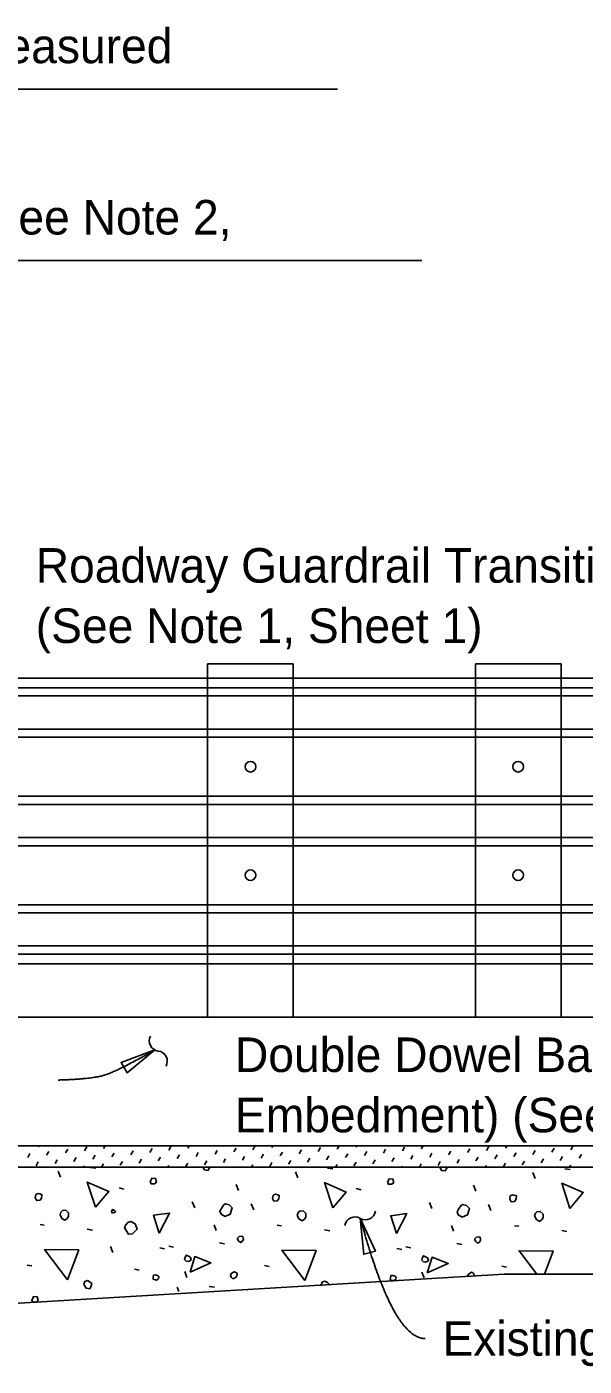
# Model space of a CAD drawing. Extents: x 0 to 41.1, y 0 to 25.9.
# Drawn here: x 30.12 to 33.37, y 5.83 to 13.65 of the extents above; entities that cross this region are included whole.
import ezdxf

# ---------------------------------------------------------------- set-up
doc = ezdxf.new("R2010")
doc.units = 0
for name, color, linetype in [('Dimension', 7, 'Continuous'), ('ExistSuperStruct', 7, 'Continuous'), ('Miscellaneous', 7, 'Continuous'), ('SteelMisc_h', 7, 'Continuous'), ('TextStructures', 7, 'Continuous')]:
    doc.layers.add(name, color=color, linetype=linetype)

msp = doc.modelspace()

# ---------------------------------------------------------------- linework, layer by layer
at = {"layer": 'Dimension'}
for p, q in [((31.9321, 13.2856), (20.3986, 13.2856)), ((32.4255, 12.2857), (27.1158, 12.2857))]:
    msp.add_line(p, q, dxfattribs=at)
for points in [[(30.8674, 7.6796), (30.7047, 7.5449), (30.6694, 7.606)], [(32.0659, 6.6961), (32.086, 6.4858), (32.1541, 6.5042)]]:
    msp.add_lwpolyline(points, close=True, dxfattribs=at)
for centre, start, end in [((30.894, 7.7311), 151.52667, 263.25389), ((30.88, 7.6127), 331.52667, 83.25389), ((32.096, 6.7468), 239.26505, 350.99227), ((32.0351, 6.6444), 59.26505, 170.99227)]:
    msp.add_arc(centre, 0.0596, start, end, dxfattribs=at)
for points in [[(30.3034, 7.5026), (30.4844, 7.5075), (30.6433, 7.5501), (30.8674, 7.6796)], [(32.0663, 6.6959), (32.2554, 5.9941), (32.4446, 5.9941)]]:
    msp.add_open_spline(points, degree=2, dxfattribs=at)
at = {"layer": 'ExistSuperStruct'}
for p, q in [((27.6853, 7.8689), (35.7954, 7.8689)), ((39.26, 7.1191), (27.6853, 7.1191)), ((27.6853, 6.994), (39.26, 6.994)), ((32.9053, 6.369), (28.6853, 6.119)), ((39.26, 6.369), (32.9053, 6.369))]:
    msp.add_line(p, q, dxfattribs=at)
at = {"layer": 'Miscellaneous'}
for p, q in [((31.1749, 9.9315), (31.1749, 7.869)), ((31.1749, 9.9315), (31.6749, 9.9315)), ((31.6749, 9.9315), (31.6749, 7.869)), ((32.7374, 9.9315), (32.7374, 7.869)), ((32.7374, 9.9315), (33.2374, 9.9315)), ((33.2374, 9.9315), (33.2374, 7.869)), ((26.2319, 9.7925), (37.5468, 9.7925)), ((26.2319, 9.7443), (37.5468, 9.7443)), ((26.2319, 9.5515), (37.5468, 9.5515)), ((26.2319, 9.5032), (37.5468, 9.5032)), ((26.2319, 9.1593), (37.5468, 9.1593)), ((26.2319, 9.1111), (37.5468, 9.1111)), ((26.2319, 8.9182), (37.5468, 8.9182)), ((26.2319, 8.8701), (37.5468, 8.8701)), ((26.2319, 8.5262), (37.5468, 8.5262)), ((26.2319, 8.4779), (37.5468, 8.4779)), ((26.2319, 8.2851), (37.5468, 8.2851)), ((26.2319, 8.2369), (37.5468, 8.2369)), ((30.1865, 7.1128), (30.1901, 7.1191)), ((30.5673, 7.1029), (30.5766, 7.1191)), ((30.6779, 7.1158), (30.6798, 7.1191)), ((30.948, 7.0929), (30.961, 7.1153)), ((31.0586, 7.1059), (31.0663, 7.1191)), ((31.1693, 7.1189), (31.1694, 7.1191)), ((31.4394, 7.096), (31.4523, 7.1183)), ((31.55, 7.1089), (31.5559, 7.1191)), ((31.9307, 7.099), (31.9424, 7.1191)), ((32.0414, 7.1119), (32.0455, 7.1191)), ((32.4221, 7.102), (32.432, 7.1191)), ((32.5327, 7.115), (32.5351, 7.1191)), ((32.8028, 7.0921), (32.8158, 7.1144)), ((32.9135, 7.105), (32.9216, 7.1191)), ((33.0241, 7.118), (33.0247, 7.1191)), ((33.2942, 7.0951), (33.3072, 7.1175)), ((30.1247, 7.051), (30.1377, 7.0734)), ((30.2354, 7.064), (30.2483, 7.0864)), ((30.2842, 7.0152), (30.2972, 7.0375)), ((30.346, 7.077), (30.359, 7.0993)), ((30.3948, 7.0281), (30.4078, 7.0505)), ((30.4566, 7.0899), (30.4696, 7.1123)), ((30.5055, 7.0411), (30.5184, 7.0635)), ((30.6161, 7.054), (30.6291, 7.0764)), ((30.7267, 7.067), (30.7397, 7.0894)), ((30.7756, 7.0182), (30.7885, 7.0406)), ((30.8374, 7.08), (30.8503, 7.1024)), ((30.8862, 7.0311), (30.8992, 7.0535)), ((30.9968, 7.0441), (31.0098, 7.0665)), ((31.1075, 7.0571), (31.1204, 7.0795)), ((31.2181, 7.07), (31.2311, 7.0924)), ((31.2669, 7.0212), (31.2799, 7.0436)), ((31.3287, 7.083), (31.3417, 7.1054)), ((31.3776, 7.0342), (31.3905, 7.0566)), ((31.4882, 7.0471), (31.5012, 7.0695)), ((31.5988, 7.0601), (31.6118, 7.0825)), ((31.7095, 7.073), (31.7224, 7.0954)), ((31.7583, 7.0242), (31.7713, 7.0466)), ((31.8201, 7.086), (31.8331, 7.1084)), ((31.8689, 7.0372), (31.8819, 7.0596)), ((31.9796, 7.0501), (31.9925, 7.0725)), ((32.0902, 7.0631), (32.1032, 7.0855)), ((32.139, 7.0143), (32.152, 7.0367)), ((32.2008, 7.0761), (32.2138, 7.0985)), ((32.2497, 7.0272), (32.2626, 7.0496)), ((32.3115, 7.089), (32.3244, 7.1114)), ((32.3603, 7.0402), (32.3733, 7.0626)), ((32.4709, 7.0532), (32.4839, 7.0756)), ((32.5816, 7.0661), (32.5945, 7.0885)), ((32.6304, 7.0173), (32.6434, 7.0397)), ((32.6922, 7.0791), (32.7052, 7.1015)), ((32.741, 7.0303), (32.754, 7.0526)), ((32.8517, 7.0432), (32.8646, 7.0656)), ((32.9623, 7.0562), (32.9753, 7.0786)), ((33.0729, 7.0691), (33.0859, 7.0915)), ((33.1218, 7.0203), (33.1347, 7.0427)), ((33.1836, 7.0821), (33.1965, 7.1045)), ((33.2324, 7.0333), (33.2454, 7.0557)), ((33.343, 7.0462), (33.356, 7.0686)), ((30.1736, 7.0022), (30.1865, 7.0246)), ((30.317, 6.9356), (30.3029, 6.971)), ((30.4522, 6.994), (30.4566, 7.0017)), ((30.4896, 6.9916), (30.5214, 6.988)), ((30.5553, 6.994), (30.5673, 7.0146)), ((30.6649, 7.0052), (30.6779, 7.0276)), ((30.9418, 6.994), (30.948, 7.0047)), ((31.0457, 6.9953), (31.0586, 7.0177)), ((31.1563, 7.0082), (31.1693, 7.0306)), ((31.3283, 6.994), (31.3287, 6.9948)), ((31.4314, 6.994), (31.4394, 7.0077)), ((31.537, 6.9983), (31.55, 7.0207)), ((31.6477, 7.0113), (31.6606, 7.0336)), ((31.7017, 6.9321), (31.6875, 6.9675)), ((31.8179, 6.994), (31.8201, 6.9978)), ((31.8743, 6.988), (31.9061, 6.9845)), ((31.921, 6.994), (31.9307, 7.0107)), ((32.0284, 7.0013), (32.0414, 7.0237)), ((32.3075, 6.994), (32.3115, 7.0008)), ((32.4107, 6.994), (32.4221, 7.0138)), ((32.5198, 7.0043), (32.5327, 7.0267)), ((32.7972, 6.994), (32.8028, 7.0038)), ((32.9005, 6.9944), (32.9135, 7.0168)), ((33.0111, 7.0073), (33.0241, 7.0297)), ((33.0864, 6.9286), (33.0722, 6.9639)), ((33.259, 6.9845), (33.2908, 6.981)), ((33.2868, 6.994), (33.2942, 7.0068)), ((31.3558, 6.8572), (31.3417, 6.8926)), ((32.7405, 6.8537), (32.7264, 6.889)), ((30.6576, 6.8731), (30.6858, 6.8661)), ((32.0422, 6.8696), (32.0705, 6.8625)), ((31.0995, 6.7565), (31.0854, 6.7918)), ((31.4436, 6.7447), (31.4294, 6.7801)), ((32.4842, 6.7529), (32.47, 6.7883)), ((32.8283, 6.7412), (32.8141, 6.7765)), ((30.1968, 6.6599), (30.2215, 6.6563)), ((31.225, 6.6239), (31.2126, 6.6575)), ((31.5815, 6.6563), (31.6062, 6.6528)), ((32.6097, 6.6203), (32.5973, 6.6539)), ((32.9661, 6.6528), (32.9909, 6.6493)), ((30.4726, 6.6316), (30.5026, 6.6263)), ((31.8572, 6.628), (31.8873, 6.6227)), ((33.2419, 6.6245), (33.272, 6.6192)), ((30.6211, 6.4972), (30.6087, 6.5308)), ((30.8951, 6.5237), (30.9233, 6.5167)), ((30.9475, 6.5337), (30.9758, 6.5267)), ((31.2438, 6.552), (31.2739, 6.5467)), ((32.2797, 6.5202), (32.308, 6.5131)), ((32.3321, 6.5302), (32.3604, 6.5231)), ((32.6285, 6.5485), (32.6586, 6.5432)), ((30.1225, 6.423), (30.1491, 6.4177)), ((31.5072, 6.4194), (31.5337, 6.4141)), ((32.8919, 6.4159), (32.9184, 6.4106)), ((30.7483, 6.3982), (30.7749, 6.3929)), ((31.0535, 6.3511), (31.0412, 6.3847)), ((32.4382, 6.3476), (32.4258, 6.3812)), ((31.0076, 6.2682), (30.997, 6.2947)), ((31.1837, 6.2975), (31.2155, 6.2939))]:
    msp.add_line(p, q, dxfattribs=at)
for points in [[(31.1478, 6.994), (31.1561, 6.9792), (31.1773, 6.9757), (31.1861, 6.9916), (31.1867, 6.994)], [(32.5307, 6.994), (32.5319, 6.9916)], [(32.5319, 6.9916), (32.5407, 6.9757), (32.562, 6.9721), (32.5708, 6.988), (32.5723, 6.994)], [(30.5203, 6.7606), (30.4726, 6.9074), (30.5981, 6.8525), (30.5203, 6.7606)], [(30.8449, 6.8979), (30.8662, 6.8979), (30.8768, 6.9085), (30.8715, 6.9279), (30.8485, 6.9297), (30.8449, 6.9191), (30.8396, 6.9103), (30.8449, 6.8979), (30.8414, 6.9014)], [(31.905, 6.7571), (31.8572, 6.9038), (31.9828, 6.849), (31.905, 6.7571)], [(32.2296, 6.8944), (32.2508, 6.8944), (32.2614, 6.905), (32.2561, 6.9244), (32.2332, 6.9262), (32.2296, 6.9156), (32.2243, 6.9067), (32.2296, 6.8944), (32.2261, 6.8979)], [(33.2896, 6.7536), (33.2419, 6.9003), (33.3674, 6.8455), (33.2896, 6.7536)], [(30.1685, 6.8154), (30.1773, 6.7995), (30.1968, 6.8013), (30.2056, 6.8137), (30.2074, 6.8331), (30.195, 6.8384), (30.1862, 6.8402), (30.1756, 6.8366), (30.172, 6.8331), (30.1685, 6.8154)], [(31.5532, 6.8119), (31.562, 6.796), (31.5815, 6.7977), (31.5903, 6.8101), (31.5921, 6.8296), (31.5797, 6.8349), (31.5709, 6.8366), (31.5603, 6.8331), (31.5567, 6.8296), (31.5532, 6.8119)], [(32.9379, 6.8084), (32.9467, 6.7924), (32.9661, 6.7942), (32.975, 6.8066), (32.9768, 6.826), (32.9644, 6.8313), (32.9555, 6.8331), (32.9449, 6.8296), (32.9414, 6.826), (32.9379, 6.8084)], [(30.3135, 6.7164), (30.3241, 6.6952), (30.3418, 6.6846), (30.3559, 6.6952), (30.363, 6.7058), (30.363, 6.727), (30.3471, 6.7429), (30.3276, 6.7412), (30.3188, 6.7323), (30.3135, 6.7164)], [(30.6193, 6.7253), (30.6387, 6.7341), (30.6317, 6.7412), (30.6193, 6.7465), (30.614, 6.7341), (30.6193, 6.7253)], [(30.8927, 6.6097), (30.8591, 6.714), (30.9528, 6.7264), (30.8927, 6.6097)], [(31.2533, 6.7193), (31.2763, 6.707), (31.3063, 6.7193), (31.3187, 6.7565), (31.301, 6.7741), (31.278, 6.7794), (31.2674, 6.7724), (31.2551, 6.7529), (31.2462, 6.737), (31.2533, 6.7193)], [(31.6981, 6.7129), (31.7088, 6.6917), (31.7264, 6.6811), (31.7406, 6.6917), (31.7476, 6.7023), (31.7476, 6.7235), (31.7317, 6.7394), (31.7123, 6.7376), (31.7034, 6.7288), (31.6981, 6.7129)], [(32.2773, 6.6062), (32.2438, 6.7105), (32.3374, 6.7229), (32.2773, 6.6062)], [(32.638, 6.7158), (32.661, 6.7034), (32.691, 6.7158), (32.7034, 6.7529), (32.6857, 6.7706), (32.6627, 6.7759), (32.6521, 6.7688), (32.6397, 6.7494), (32.6309, 6.7335), (32.638, 6.7158)], [(33.0828, 6.7094), (33.0934, 6.6881), (33.1111, 6.6775), (33.1252, 6.6881), (33.1323, 6.6988), (33.1323, 6.72), (33.1164, 6.7359), (33.097, 6.7341), (33.0881, 6.7253), (33.0828, 6.7094)], [(30.69, 6.6404), (30.713, 6.6033), (30.736, 6.6051), (30.7448, 6.6139), (30.7642, 6.6333), (30.7519, 6.6634), (30.7271, 6.6775), (30.7094, 6.6705), (30.6953, 6.6563), (30.69, 6.6404)], [(31.3552, 6.5644), (31.3658, 6.5538), (31.3764, 6.5609), (31.3835, 6.5715), (31.3799, 6.5892), (31.3711, 6.5909), (31.3587, 6.5892), (31.3481, 6.5785), (31.3552, 6.5644)], [(32.7399, 6.5609), (32.7505, 6.5503), (32.7611, 6.5573), (32.7682, 6.5679), (32.7646, 6.5856), (32.7558, 6.5874), (32.7434, 6.5856), (32.7328, 6.575), (32.7399, 6.5609)], [(30.3577, 6.3364), (30.2233, 6.5131), (30.4231, 6.5114), (30.3577, 6.3364)], [(31.7423, 6.3328), (31.608, 6.5096), (31.8077, 6.5078), (31.7423, 6.3328)], [(33.0969, 6.369), (32.9927, 6.5061), (33.1924, 6.5043), (33.1418, 6.369)], [(31.05, 6.4453), (31.0624, 6.4436), (31.0747, 6.4489), (31.0783, 6.4595), (31.073, 6.4683), (31.0624, 6.4754), (31.05, 6.4807), (31.0429, 6.4666), (31.0394, 6.4559), (31.05, 6.4453)], [(31.0724, 6.3806), (31.1006, 6.4725), (31.1943, 6.4354), (31.0724, 6.3806)], [(32.4347, 6.4418), (32.4471, 6.44), (32.4594, 6.4453), (32.463, 6.4559), (32.4577, 6.4648), (32.4471, 6.4719), (32.4347, 6.4772), (32.4276, 6.463), (32.4241, 6.4524), (32.4347, 6.4418)], [(32.457, 6.377), (32.4853, 6.4689), (32.579, 6.4318), (32.457, 6.377)], [(30.4567, 6.3045), (30.4655, 6.2886), (30.4867, 6.2851), (30.4955, 6.301), (30.4991, 6.3151), (30.4902, 6.324), (30.4743, 6.3328), (30.4584, 6.3275), (30.4531, 6.3116), (30.4567, 6.3045)], [(30.8562, 6.3399), (30.8756, 6.3346), (30.888, 6.3434), (30.8898, 6.3558), (30.8862, 6.3593), (30.8721, 6.3664), (30.8597, 6.3646), (30.8579, 6.3523), (30.8562, 6.3399)], [(31.3198, 6.3452), (31.3269, 6.3452), (31.3411, 6.3523), (31.3464, 6.3682), (31.3446, 6.377), (31.3304, 6.3841), (31.3128, 6.3735), (31.3092, 6.3629), (31.3128, 6.3523), (31.3198, 6.3452)], [(32.2408, 6.3364), (32.2603, 6.3311), (32.2727, 6.3399), (32.2744, 6.3523), (32.2709, 6.3558), (32.2568, 6.3629), (32.2444, 6.3611), (32.2426, 6.3487), (32.2408, 6.3364)], [(32.7288, 6.3579), (32.731, 6.3646), (32.7293, 6.3735), (32.7151, 6.3806), (32.6974, 6.3699), (32.6939, 6.3593), (32.6951, 6.3558)], [(31.8821, 6.305), (31.8838, 6.3116), (31.8749, 6.3205), (31.859, 6.3293), (31.8431, 6.324), (31.8378, 6.3081), (31.8406, 6.3024)], [(30.1544, 6.2073), (30.1756, 6.2073), (30.1862, 6.2179), (30.1809, 6.2374), (30.1579, 6.2391), (30.1544, 6.2285), (30.1491, 6.2197), (30.1544, 6.2073), (30.1508, 6.2109)]]:
    msp.add_lwpolyline(points, dxfattribs=at)
at = {"layer": 'SteelMisc_h'}
for p, q in [((37.5468, 9.848), (26.2319, 9.848)), ((37.5468, 8.1814), (26.2319, 8.1814))]:
    msp.add_line(p, q, dxfattribs=at)
for centre in [(31.4249, 9.3314), (32.9874, 9.3314), (31.4249, 8.6982), (32.9874, 8.6982)]:
    msp.add_circle(centre, 0.0312, dxfattribs=at)

# ---------------------------------------------------------------- texts
at = {"layer": 'Dimension'}
for s, p in [('Roadway Guardrail Transition', (30.1716, 10.4055)), ('(See Note 1, Sheet 1)', (30.1716, 10.0535)), ('Double Dowel Bars 4D (10" ', (31.3343, 7.5496)), ('Embedment) (See Note 2)', (31.3343, 7.1976))]:
    msp.add_text(s, height=0.2016, dxfattribs=at).set_placement(p)
at = {"layer": 'TextStructures'}
for s, p in [('Post Spacing as measured', (27.7475, 13.4375)), ('End Deck Joint (See Note 2,', (27.9128, 12.4375)), ('Existing Approach Slab', (32.5454, 5.8934))]:
    msp.add_text(s, height=0.2016, dxfattribs=at).set_placement(p)

doc.saveas('drawing.dxf')
